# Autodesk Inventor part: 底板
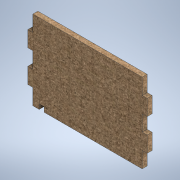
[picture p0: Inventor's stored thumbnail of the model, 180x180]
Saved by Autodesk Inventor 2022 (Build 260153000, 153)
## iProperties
Created: 2024-11
Part Number: 底板
Material: MDF 中密度繊維ボード
Document SubType Name: Modeling
Designer: shimizu
Density: 0.8 g/cm^3
Appearance: ダンボール - 段ボール紙
Author: shimizu
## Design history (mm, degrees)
sketch "スケッチ1"
  geometry: L1 (-25.119, 10.226)-(29.881, 10.226); L2 (29.881, -29.774)-(-25.119, -29.774); L3 (-25.119, 2.226)-(-27.619, 2.226); L4 (-27.619, 2.226)-(-27.619, -5.774); L5 (-27.619, -5.774)-(-25.119, -5.774); L6 (-25.119, -13.774)-(-27.619, -13.774); L7 (-27.619, -13.774)-(-27.619, -21.774); L8 (-27.619, -21.774)-(-25.119, -21.774); L9 (29.881, 2.226)-(32.381, 2.226); L10 (32.381, 2.226)-(32.381, -5.774); L11 (32.381, -5.774)-(29.881, -5.774); L12 (29.881, -13.774)-(32.381, -13.774); L13 (32.381, -13.774)-(32.381, -21.774); L14 (32.381, -21.774)-(29.881, -21.774); L15 (-25.119, 2.226)-(-25.119, 10.226); L16 (-25.119, -29.774)-(-25.119, -21.774); L17 (-25.119, -13.774)-(-25.119, -5.774); L18 (29.881, 10.226)-(29.881, 2.226); L19 (29.881, -5.774)-(29.881, -13.774); L20 (29.881, -21.774)-(29.881, -29.774); L21 (-21.939, -29.774)-(-19.429, -29.774); L22 (-19.429, -29.774)-(-19.429, -27.274); L23 (-19.429, -27.274)-(-21.939, -27.274); L24 (-21.939, -27.274)-(-21.939, -29.774); 2 further points
  constraints: 48 end point, 16 parallel, 8 perpendicular, 6 horizontal, 1 point on line
  dimensions: "d16" = 60 distance between parallel lines of L13 L7; "d17" = 2.51 distance between parallel lines of L22 L24; "d18" = 2.5 distance between parallel lines of L2 L23; "d19" = 3.18 distance between parallel lines of L16 L24
extrude "押し出し1" new body sketch "スケッチ1" distance "d2" = 2.5; taper "d3" = 0 deg
node "ソリッド1"
